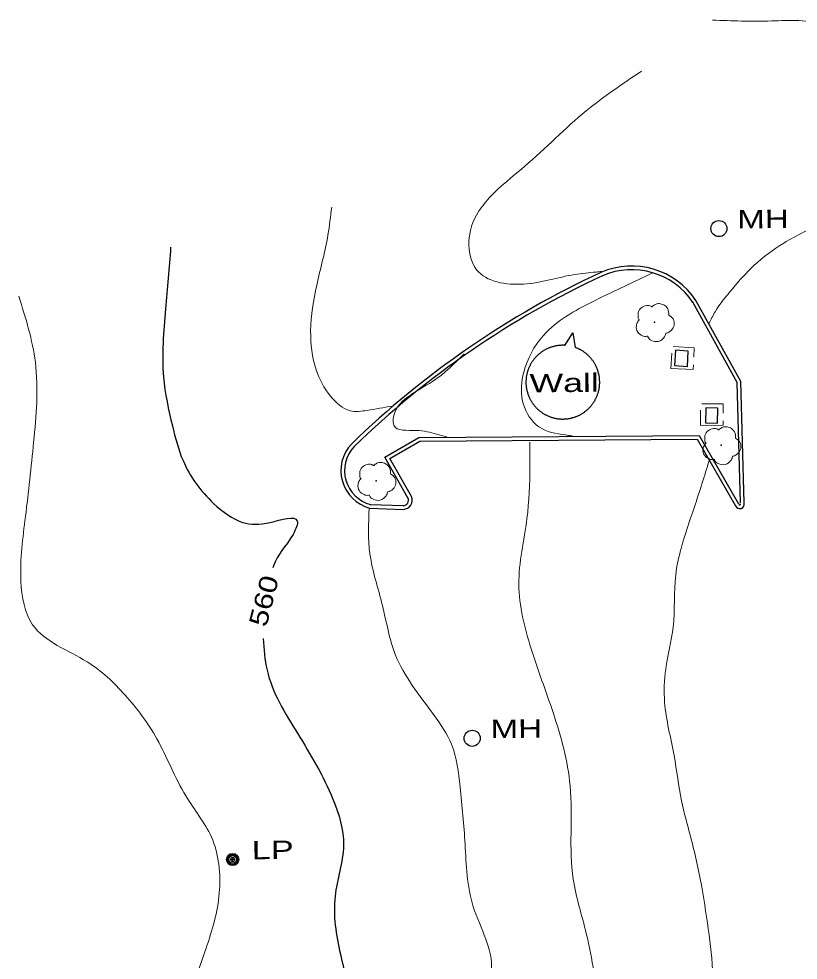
# Model space of a CAD drawing. Extents: x 2361708 to 2370558, y 6977955 to 6991887.
# Drawn here: x 2367402.6 to 2367606.3, y 6988537.8 to 6988783.9 of the extents above; entities that cross this region are included whole.
import ezdxf
from ezdxf.enums import TextEntityAlignment as Align

# ---------------------------------------------------------------- set-up
doc = ezdxf.new("R2010")
doc.units = 0
doc.header["$LTSCALE"] = 1.9
for name, color, linetype, lineweight in [('14', 7, 'Continuous', 13), ('18', 7, 'Continuous', 25), ('2', 7, 'Continuous', 25), ('20', 7, 'Continuous', 25), ('23', 7, 'Continuous', 25), ('29', 7, 'Continuous', 13), ('31', 7, 'Continuous', 13), ('35', 7, 'Continuous', 13)]:
    doc.layers.add(name, color=color, linetype=linetype, lineweight=lineweight)

msp = doc.modelspace()

# ---------------------------------------------------------------- linework, layer by layer
at = {"layer": '14'}
for p, q in [((2367573.045, 6988692.521), (2367573.267, 6988696.513)), ((2367580.787, 6988677.644), (2367580.769, 6988681.644))]:
    msp.add_line(p, q, dxfattribs=at)
for points in [[(2367573.631, 6988698.227), (2367579.154, 6988697.93), (2367579.017, 6988695.468)], [(2367578.906, 6988693.467), (2367578.838, 6988692.206), (2367573.045, 6988692.521)], [(2367581.153, 6988683.258), (2367586.694, 6988683.28), (2367586.707, 6988680.82)], [(2367586.716, 6988678.82), (2367586.717, 6988677.67), (2367580.787, 6988677.644)]]:
    msp.add_lwpolyline(points, dxfattribs=at)
at = {"layer": '18'}
for points in [[(2367545.336, 6988698.548), (2367547.375, 6988701.827), (2367548.042, 6988697.983)], [(2367545.346, 6988698.558), (2367545.296, 6988698.557), (2367545.136, 6988698.566), (2367544.966, 6988698.574), (2367544.796, 6988698.573), (2367544.626, 6988698.571), (2367544.456, 6988698.569), (2367544.296, 6988698.558), (2367544.126, 6988698.556), (2367543.956, 6988698.535), (2367543.786, 6988698.523), (2367543.617, 6988698.501), (2367543.457, 6988698.48), (2367543.287, 6988698.458), (2367543.117, 6988698.436), (2367542.957, 6988698.405), (2367542.788, 6988698.363), (2367542.628, 6988698.332), (2367542.469, 6988698.29), (2367542.299, 6988698.249), (2367542.139, 6988698.207), (2367541.98, 6988698.156), (2367541.82, 6988698.104), (2367541.661, 6988698.053), (2367541.501, 6988698.001), (2367541.342, 6988697.94), (2367541.182, 6988697.878), (2367541.023, 6988697.816), (2367540.874, 6988697.745), (2367540.724, 6988697.684), (2367540.565, 6988697.612), (2367540.416, 6988697.531), (2367540.266, 6988697.459), (2367540.117, 6988697.378), (2367539.978, 6988697.296), (2367539.829, 6988697.205), (2367539.69, 6988697.124), (2367539.541, 6988697.032), (2367539.401, 6988696.941), (2367539.262, 6988696.839), (2367539.123, 6988696.748), (2367538.994, 6988696.647), (2367538.855, 6988696.545), (2367538.726, 6988696.434), (2367538.597, 6988696.333), (2367538.468, 6988696.222), (2367538.339, 6988696.111), (2367538.22, 6988695.999), (2367538.092, 6988695.888), (2367537.972, 6988695.767), (2367537.854, 6988695.646), (2367537.735, 6988695.525), (2367537.626, 6988695.404), (2367537.517, 6988695.273), (2367537.408, 6988695.152), (2367537.3, 6988695.021), (2367537.19, 6988694.89), (2367537.092, 6988694.749), (2367536.983, 6988694.618), (2367536.894, 6988694.477), (2367536.796, 6988694.346), (2367536.697, 6988694.205), (2367536.608, 6988694.064), (2367536.52, 6988693.913), (2367536.441, 6988693.773), (2367536.353, 6988693.621), (2367536.274, 6988693.481), (2367536.196, 6988693.33), (2367536.117, 6988693.18), (2367536.048, 6988693.029), (2367535.98, 6988692.878), (2367535.911, 6988692.717), (2367535.843, 6988692.567), (2367535.784, 6988692.406), (2367535.726, 6988692.256), (2367535.667, 6988692.095), (2367535.609, 6988691.935), (2367535.56, 6988691.774), (2367535.512, 6988691.614), (2367535.473, 6988691.454), (2367535.425, 6988691.283), (2367535.387, 6988691.122), (2367535.348, 6988690.962), (2367535.32, 6988690.792), (2367535.281, 6988690.632), (2367535.253, 6988690.461), (2367535.234, 6988690.301), (2367535.206, 6988690.131), (2367535.187, 6988689.96), (2367535.169, 6988689.8), (2367535.161, 6988689.63), (2367535.152, 6988689.46), (2367535.144, 6988689.29), (2367535.136, 6988689.12), (2367535.137, 6988688.96), (2367535.138, 6988688.79), (2367535.14, 6988688.62), (2367535.142, 6988688.45), (2367535.154, 6988688.28), (2367535.165, 6988688.12), (2367535.187, 6988687.95)], [(2367554.321, 6988687.573), (2367554.34, 6988687.732), (2367554.358, 6988687.903), (2367554.377, 6988688.073), (2367554.385, 6988688.243), (2367554.403, 6988688.403), (2367554.412, 6988688.574), (2367554.41, 6988688.744), (2367554.418, 6988688.913), (2367554.417, 6988689.083), (2367554.405, 6988689.253), (2367554.404, 6988689.413), (2367554.392, 6988689.583), (2367554.381, 6988689.753), (2367554.369, 6988689.923), (2367554.347, 6988690.083), (2367554.325, 6988690.252), (2367554.294, 6988690.422), (2367554.273, 6988690.582), (2367554.241, 6988690.752), (2367554.209, 6988690.922), (2367554.168, 6988691.081), (2367554.136, 6988691.241), (2367554.095, 6988691.411), (2367554.043, 6988691.57), (2367554.002, 6988691.73), (2367553.95, 6988691.889), (2367553.899, 6988692.049), (2367553.837, 6988692.208), (2367553.786, 6988692.368), (2367553.724, 6988692.527), (2367553.653, 6988692.676), (2367553.591, 6988692.836), (2367553.52, 6988692.985), (2367553.448, 6988693.144), (2367553.377, 6988693.294), (2367553.296, 6988693.443), (2367553.214, 6988693.592), (2367553.133, 6988693.731), (2367553.051, 6988693.881), (2367552.96, 6988694.02), (2367552.868, 6988694.169), (2367552.777, 6988694.308), (2367552.686, 6988694.447), (2367552.584, 6988694.586), (2367552.483, 6988694.715), (2367552.382, 6988694.854), (2367552.281, 6988694.983), (2367552.169, 6988695.112), (2367552.068, 6988695.242), (2367551.957, 6988695.37), (2367551.836, 6988695.489), (2367551.724, 6988695.618), (2367551.603, 6988695.737), (2367551.482, 6988695.856), (2367551.361, 6988695.965), (2367551.24, 6988696.084), (2367551.119, 6988696.192), (2367550.988, 6988696.301), (2367550.857, 6988696.41), (2367550.726, 6988696.519), (2367550.595, 6988696.617), (2367550.454, 6988696.716), (2367550.323, 6988696.815), (2367550.182, 6988696.913), (2367550.041, 6988697.002), (2367549.9, 6988697.101), (2367549.759, 6988697.189), (2367549.609, 6988697.268), (2367549.468, 6988697.356), (2367549.317, 6988697.435), (2367549.166, 6988697.514), (2367549.016, 6988697.593), (2367548.865, 6988697.661), (2367548.714, 6988697.73), (2367548.564, 6988697.798), (2367548.403, 6988697.867), (2367548.252, 6988697.925), (2367548.092, 6988697.984), (2367548.052, 6988698.003)], [(2367535.187, 6988687.95), (2367535.208, 6988687.78), (2367535.23, 6988687.611), (2367535.251, 6988687.451), (2367535.273, 6988687.281), (2367535.305, 6988687.111), (2367535.336, 6988686.952), (2367535.378, 6988686.782), (2367535.419, 6988686.622), (2367535.461, 6988686.463), (2367535.503, 6988686.293), (2367535.544, 6988686.134), (2367535.596, 6988685.974), (2367535.657, 6988685.815), (2367535.708, 6988685.655), (2367535.77, 6988685.496), (2367535.831, 6988685.346), (2367535.893, 6988685.187), (2367535.964, 6988685.038), (2367536.026, 6988684.878), (2367536.097, 6988684.729), (2367536.179, 6988684.58), (2367536.25, 6988684.43), (2367536.331, 6988684.281), (2367536.413, 6988684.132), (2367536.504, 6988683.993), (2367536.586, 6988683.844), (2367536.677, 6988683.704), (2367536.768, 6988683.565), (2367536.87, 6988683.426), (2367536.961, 6988683.287), (2367537.062, 6988683.148), (2367537.164, 6988683.018), (2367537.265, 6988682.88), (2367537.376, 6988682.751), (2367537.487, 6988682.622), (2367537.598, 6988682.503), (2367537.71, 6988682.374), (2367537.821, 6988682.255), (2367537.942, 6988682.136), (2367538.063, 6988682.017), (2367538.184, 6988681.898), (2367538.306, 6988681.78), (2367538.437, 6988681.671), (2367538.558, 6988681.562), (2367538.689, 6988681.454), (2367538.82, 6988681.354), (2367538.951, 6988681.246), (2367539.092, 6988681.147), (2367539.222, 6988681.048), (2367539.364, 6988680.95), (2367539.505, 6988680.861), (2367539.645, 6988680.772), (2367539.786, 6988680.684), (2367539.937, 6988680.595), (2367540.078, 6988680.517), (2367540.228, 6988680.428), (2367540.379, 6988680.359), (2367540.53, 6988680.281), (2367540.681, 6988680.202), (2367540.831, 6988680.134), (2367540.992, 6988680.065), (2367541.143, 6988680.006), (2367541.303, 6988679.938), (2367541.454, 6988679.88), (2367541.614, 6988679.821), (2367541.775, 6988679.773)], [(2367541.775, 6988679.773), (2367541.935, 6988679.724), (2367542.096, 6988679.676), (2367542.256, 6988679.627), (2367542.416, 6988679.589), (2367542.587, 6988679.55), (2367542.747, 6988679.512), (2367542.917, 6988679.474), (2367543.078, 6988679.445), (2367543.248, 6988679.416), (2367543.408, 6988679.388), (2367543.579, 6988679.37), (2367543.749, 6988679.351), (2367543.909, 6988679.333), (2367544.079, 6988679.315), (2367544.249, 6988679.306), (2367544.419, 6988679.298), (2367544.589, 6988679.299), (2367544.749, 6988679.291), (2367544.919, 6988679.293), (2367545.09, 6988679.304), (2367545.26, 6988679.306), (2367545.429, 6988679.317), (2367545.589, 6988679.329), (2367545.759, 6988679.34), (2367545.929, 6988679.362), (2367546.099, 6988679.384), (2367546.259, 6988679.405), (2367546.428, 6988679.437), (2367546.588, 6988679.468), (2367546.758, 6988679.5), (2367546.917, 6988679.532), (2367547.087, 6988679.573), (2367547.247, 6988679.615), (2367547.406, 6988679.666), (2367547.576, 6988679.708), (2367547.735, 6988679.76), (2367547.895, 6988679.811), (2367548.054, 6988679.872), (2367548.204, 6988679.924), (2367548.363, 6988679.985), (2367548.522, 6988680.057), (2367548.672, 6988680.118), (2367548.831, 6988680.19), (2367548.98, 6988680.261), (2367549.13, 6988680.332), (2367549.279, 6988680.414), (2367549.428, 6988680.496), (2367549.577, 6988680.577), (2367549.717, 6988680.658), (2367549.866, 6988680.75), (2367550.005, 6988680.841), (2367550.144, 6988680.933), (2367550.283, 6988681.024), (2367550.422, 6988681.125), (2367550.561, 6988681.226), (2367550.69, 6988681.328), (2367550.82, 6988681.429), (2367550.958, 6988681.54), (2367551.088, 6988681.641), (2367551.206, 6988681.752), (2367551.335, 6988681.873), (2367551.454, 6988681.985), (2367551.573, 6988682.106), (2367551.692, 6988682.217), (2367551.81, 6988682.348), (2367551.92, 6988682.469), (2367552.038, 6988682.59), (2367552.147, 6988682.721), (2367552.256, 6988682.852), (2367552.355, 6988682.983), (2367552.464, 6988683.115), (2367552.562, 6988683.246), (2367552.661, 6988683.387), (2367552.75, 6988683.528), (2367552.848, 6988683.668), (2367552.937, 6988683.809), (2367553.026, 6988683.95), (2367553.115, 6988684.091), (2367553.193, 6988684.242), (2367553.271, 6988684.392), (2367553.35, 6988684.543), (2367553.429, 6988684.684), (2367553.497, 6988684.845), (2367553.576, 6988684.996), (2367553.634, 6988685.146), (2367553.703, 6988685.307), (2367553.761, 6988685.457), (2367553.83, 6988685.618), (2367553.878, 6988685.778), (2367553.937, 6988685.939), (2367553.985, 6988686.099), (2367554.034, 6988686.26), (2367554.082, 6988686.42), (2367554.121, 6988686.58), (2367554.159, 6988686.741), (2367554.198, 6988686.911), (2367554.236, 6988687.072), (2367554.264, 6988687.242), (2367554.293, 6988687.402), (2367554.321, 6988687.573)]]:
    msp.add_lwpolyline(points, dxfattribs=at)
at = {"layer": '2'}
for p, q in [((2367494.31, 6988656.96), (2367503.143, 6988656.644)), ((2367494.279, 6988656), (2367503.112, 6988655.684))]:
    msp.add_line(p, q, dxfattribs=at)
for points in [[(2367591.221, 6988657.362), (2367590.381, 6988688.816), (2367578.751, 6988709.836)], [(2367592.18, 6988657.391), (2367591.339, 6988689.075), (2367579.586, 6988710.304)], [(2367504.385, 6988658.536), (2367498.232, 6988669.318), (2367507.143, 6988674.453), (2367580.442, 6988675.03), (2367590.723, 6988657.098)], [(2367505.221, 6988659.014), (2367499.536, 6988668.96), (2367507.403, 6988673.495), (2367579.891, 6988674.065), (2367589.888, 6988656.62)]]:
    msp.add_lwpolyline(points, dxfattribs=at)
for centre, radius, start, end in [((2367562.757, 6988699.065), 20.237, 33.73783, 113.32307), ((2367562.757, 6988699.065), 19.277, 33.73783, 113.32307), ((2367655.08, 6988502.041), 237.81, 114.95543, 134.12547), ((2367655.08, 6988502.041), 236.85, 114.95543, 134.12547), ((2367496.91, 6988665.801), 10.148, 136.82148, 254.97551), ((2367496.91, 6988665.801), 9.188, 136.82148, 254.97551), ((2367502.987, 6988658.096), 1.456, 272.98097, 22.32393), ((2367502.987, 6988658.096), 2.416, 272.98097, 22.32393), ((2367591.009, 6988657.078), 1.211, 202.25533, 14.96097), ((2367591.009, 6988657.078), 0.251, 202.25533, 14.96097)]:
    msp.add_arc(centre, radius, start, end, dxfattribs=at)
at = {"layer": '20'}
for centre, radius in [((2367585.578, 6988729.082), 2.1), ((2367521.083, 6988595.812), 2.1), ((2367458.461, 6988564.134), 1.6), ((2367458.461, 6988564.134), 1.3), ((2367458.461, 6988564.134), 1), ((2367458.461, 6988564.134), 0.539), ((2367458.461, 6988564.134), 0.192)]:
    msp.add_circle(centre, radius, dxfattribs=at)
at = {"layer": '23'}
for points in [[(2367574.25, 6988697.272), (2367573.998, 6988693.25), (2367577.33, 6988693.042), (2367577.582, 6988697.064)], [(2367585.285, 6988682.107), (2367582.184, 6988682.197), (2367582.071, 6988678.296), (2367585.172, 6988678.206)]]:
    msp.add_lwpolyline(points, close=True, dxfattribs=at)
at = {"layer": '29'}
for centre in [(2367568.73, 6988704.63), (2367586.167, 6988672.445), (2367495.971, 6988663.116)]:
    msp.add_circle(centre, 0.1, dxfattribs=at)
for points in [[(2367564.764, 6988705.203), (2367564.784, 6988705.213), (2367564.703, 6988705.282), (2367564.467, 6988705.91), (2367564.505, 6988707.19), (2367565.393, 6988708.489), (2367566.698, 6988708.971), (2367567.82, 6988708.782), (2367568.051, 6988708.654), (2367568.121, 6988708.655), (2367568.171, 6988708.696), (2367568.518, 6988708.989), (2367569.384, 6988709.437), (2367570.594, 6988709.368), (2367571.71, 6988708.779), (2367572.444, 6988707.356), (2367572.452, 6988706.496)], [(2367572.442, 6988706.516), (2367573.582, 6988705.457), (2367573.867, 6988703.869), (2367573.159, 6988702.542), (2367572.505, 6988701.996), (2367571.837, 6988701.78), (2367571.687, 6988701.768), (2367571.668, 6988701.658), (2367571.346, 6988700.755), (2367569.808, 6988699.591), (2367567.915, 6988699.872), (2367567.016, 6988700.814), (2367566.945, 6988700.943), (2367566.825, 6988700.922), (2367565.614, 6988701.04), (2367564.344, 6988702.039), (2367563.998, 6988703.675), (2367564.369, 6988704.699), (2367564.695, 6988705.142), (2367564.764, 6988705.193)], [(2367582.201, 6988673.017), (2367582.221, 6988673.027), (2367582.14, 6988673.097), (2367581.904, 6988673.724), (2367581.943, 6988675.004), (2367582.83, 6988676.303), (2367584.135, 6988676.786), (2367585.257, 6988676.597), (2367585.488, 6988676.469), (2367585.558, 6988676.47), (2367585.608, 6988676.51), (2367585.955, 6988676.803), (2367586.821, 6988677.251), (2367588.031, 6988677.183), (2367589.147, 6988676.594), (2367589.881, 6988675.17), (2367589.889, 6988674.31)], [(2367589.879, 6988674.33), (2367591.019, 6988673.271), (2367591.304, 6988671.684), (2367590.597, 6988670.357), (2367589.942, 6988669.811), (2367589.274, 6988669.594), (2367589.124, 6988669.583), (2367589.105, 6988669.473), (2367588.784, 6988668.57), (2367587.245, 6988667.405), (2367585.352, 6988667.686), (2367584.453, 6988668.628), (2367584.382, 6988668.758), (2367584.262, 6988668.737), (2367583.051, 6988668.855), (2367581.781, 6988669.853), (2367581.436, 6988671.49), (2367581.806, 6988672.513), (2367582.132, 6988672.956), (2367582.201, 6988673.007)], [(2367492.005, 6988663.688), (2367492.025, 6988663.698), (2367491.945, 6988663.768), (2367491.709, 6988664.395), (2367491.747, 6988665.676), (2367492.634, 6988666.974), (2367493.939, 6988667.457), (2367495.062, 6988667.268), (2367495.293, 6988667.14), (2367495.363, 6988667.14), (2367495.413, 6988667.181), (2367495.76, 6988667.474), (2367496.625, 6988667.922), (2367497.836, 6988667.853), (2367498.952, 6988667.265), (2367499.685, 6988665.841), (2367499.693, 6988664.981)], [(2367499.683, 6988665.001), (2367500.823, 6988663.942), (2367501.108, 6988662.355), (2367500.401, 6988661.028), (2367499.747, 6988660.482), (2367499.079, 6988660.265), (2367498.929, 6988660.254), (2367498.91, 6988660.144), (2367498.588, 6988659.241), (2367497.049, 6988658.076), (2367495.156, 6988658.358), (2367494.257, 6988659.299), (2367494.186, 6988659.429), (2367494.066, 6988659.408), (2367492.855, 6988659.526), (2367491.585, 6988660.524), (2367491.24, 6988662.161), (2367491.61, 6988663.185), (2367491.936, 6988663.628), (2367492.006, 6988663.678)]]:
    msp.add_spline(points, degree=3, dxfattribs=at)
at = {"layer": '31', "lineweight": 25}
for points in [[(2367442.257, 6988724.228), (2367440.911, 6988708.074), (2367440.39, 6988690.258), (2367442.722, 6988677.5), (2367445.488, 6988668.446), (2367453.485, 6988657.241), (2367461.143, 6988652.254), (2367468.233, 6988652.271), (2367475.339, 6988652.719), (2367474.243, 6988649.128), (2367469.141, 6988640.899), (2367469.006, 6988640.408)], [(2367466.412, 6988621.952), (2367467.451, 6988613.652), (2367475.388, 6988597.137), (2367484.693, 6988579.874), (2367487.437, 6988567.84), (2367485.224, 6988554.489), (2367486.618, 6988539.401), (2367490.01, 6988525.583), (2367491.978, 6988510.041), (2367489.768, 6988495.389), (2367487.645, 6988478.868), (2367488.345, 6988465.173), (2367500.838, 6988455.472), (2367516.138, 6988441.857), (2367527.672, 6988432.016), (2367538.373, 6988418.328)]]:
    msp.add_spline(points, degree=3, dxfattribs=at)
at = {"layer": '35'}
for points in [[(2367729.15, 6988766.39), (2367723.693, 6988765.998), (2367684.8, 6988767.188), (2367656.191, 6988767.926), (2367639.03, 6988770.093), (2367623.884, 6988773.739), (2367613.085, 6988782.047), (2367599.332, 6988783.376), (2367583.908, 6988783.609)], [(2367565.364, 6988770.262), (2367550.873, 6988759.853), (2367534.681, 6988745.258), (2367520.353, 6988727.171), (2367522.237, 6988718.338), (2367534.453, 6988714.565), (2367547.87, 6988717.082), (2367553.514, 6988717.726), (2367554.873, 6988717.869)], [(2367484.349, 6988734.729), (2367483.369, 6988727.389), (2367480.443, 6988714.301), (2367478.856, 6988702.385), (2367480.314, 6988692.128), (2367484.05, 6988685.274), (2367489.206, 6988681.452), (2367493.615, 6988681.554), (2367500.135, 6988682.676)], [(2367613.063, 6988730.804), (2367602.524, 6988725.293), (2367594.829, 6988719.52), (2367589.098, 6988713.345), (2367584.575, 6988707.311), (2367583.004, 6988704.286)], [(2367568.128, 6988717.415), (2367553.424, 6988710.415), (2367540.523, 6988702.022), (2367534.95, 6988692.849), (2367534.74, 6988682.366), (2367539.263, 6988676.779), (2367546.361, 6988675.006), (2367547.392, 6988674.816)], [(2367402.567, 6988711.379), (2367406.882, 6988694.129), (2367406.43, 6988673.234), (2367404.305, 6988653.803), (2367403.116, 6988636.901), (2367406.175, 6988625.489), (2367420.458, 6988615.795), (2367430.331, 6988607.129), (2367438.65, 6988595.707), (2367446.213, 6988580.758), (2367452.896, 6988570.001), (2367454.975, 6988555.37), (2367451.532, 6988540.937), (2367447.135, 6988524.865), (2367447.728, 6988507.699), (2367444.823, 6988489.271), (2367445.285, 6988476.534), (2367449.148, 6988462.501), (2367455.047, 6988450.076), (2367461.541, 6988437.128), (2367473.347, 6988421.799), (2367482.812, 6988410.819), (2367490.447, 6988401.951), (2367502.604, 6988391.796), (2367516.985, 6988381.242), (2367523.959, 6988376.738), (2367520.83, 6988372.359), (2367510.468, 6988367.329), (2367495.128, 6988361.963), (2367480.289, 6988356.572), (2367471.574, 6988350.659), (2367469.568, 6988345.979)], [(2367518.946, 6988696.356), (2367510.704, 6988689.127), (2367500.437, 6988679.309), (2367500.572, 6988677.69), (2367506.496, 6988676.317), (2367511.776, 6988675.317), (2367514.423, 6988674.602)], [(2367536.157, 6988673.209), (2367536.187, 6988666.889), (2367535.387, 6988653.291), (2367533.28, 6988636.08), (2367536.491, 6988619.23), (2367542.22, 6988602.573), (2367546.683, 6988583.355), (2367547.505, 6988559.011), (2367550.92, 6988544.773), (2367555.082, 6988524.692), (2367559.86, 6988509.146), (2367563.377, 6988490.509), (2367566.369, 6988476.637), (2367569.778, 6988466.339), (2367571.841, 6988457.608), (2367573.712, 6988453.336)], [(2367583.045, 6988668.415), (2367579.189, 6988656.358), (2367575.703, 6988645.444), (2367574.279, 6988638.51), (2367573.629, 6988624.913), (2367571.673, 6988613.934), (2367571.385, 6988605.261), (2367573.858, 6988591.354), (2367575.811, 6988579.502), (2367578.139, 6988570.244), (2367581.075, 6988557.011), (2367582.995, 6988544.418), (2367583.892, 6988532.177), (2367581.528, 6988512.553), (2367582.181, 6988501.809), (2367585.148, 6988489.557), (2367589.522, 6988479.667), (2367594.049, 6988471.53), (2367600.856, 6988467.705), (2367608.439, 6988467.447), (2367615.482, 6988468.234), (2367619.74, 6988469.535)], [(2367494.119, 6988655.978), (2367494.363, 6988644.02), (2367497.621, 6988630.56), (2367500.963, 6988617.751), (2367510.983, 6988602.026), (2367515.687, 6988594.24), (2367517.924, 6988583.131), (2367519.216, 6988568.143), (2367521.372, 6988551.792), (2367526.04, 6988535.186), (2367519.175, 6988522.08), (2367515.788, 6988510.157), (2367516.967, 6988500.808), (2367522.057, 6988492.356), (2367528.834, 6988484.35), (2367535.578, 6988474.504), (2367541.621, 6988463.781), (2367546.888, 6988456.76), (2367549.665, 6988453.927)]]:
    msp.add_spline(points, degree=3, dxfattribs=at)

# ---------------------------------------------------------------- texts
at = {"layer": '18', "width": 1.45}
msp.add_text('Wall', height=4.8, rotation=0.545, dxfattribs=at).set_placement((2367536.103, 6988686.259))
at = {"layer": '20'}
for s, width, p in [('  MH', 1.35, (2367585.577, 6988729.082)), ('  MH', 1.35, (2367521.083, 6988595.812)), ('  LP', 1.4, (2367458.462, 6988564.134))]:
    msp.add_text(s, height=4.8, rotation=0.545, dxfattribs=dict(at, width=width)).set_placement(p)
at = {"layer": '31', "width": 1.25}
msp.add_text(' 560 ', height=4.8, rotation=75.481, dxfattribs=at).set_placement((2367468.929, 6988631.147), align=Align.CENTER)

doc.saveas('drawing.dxf')
